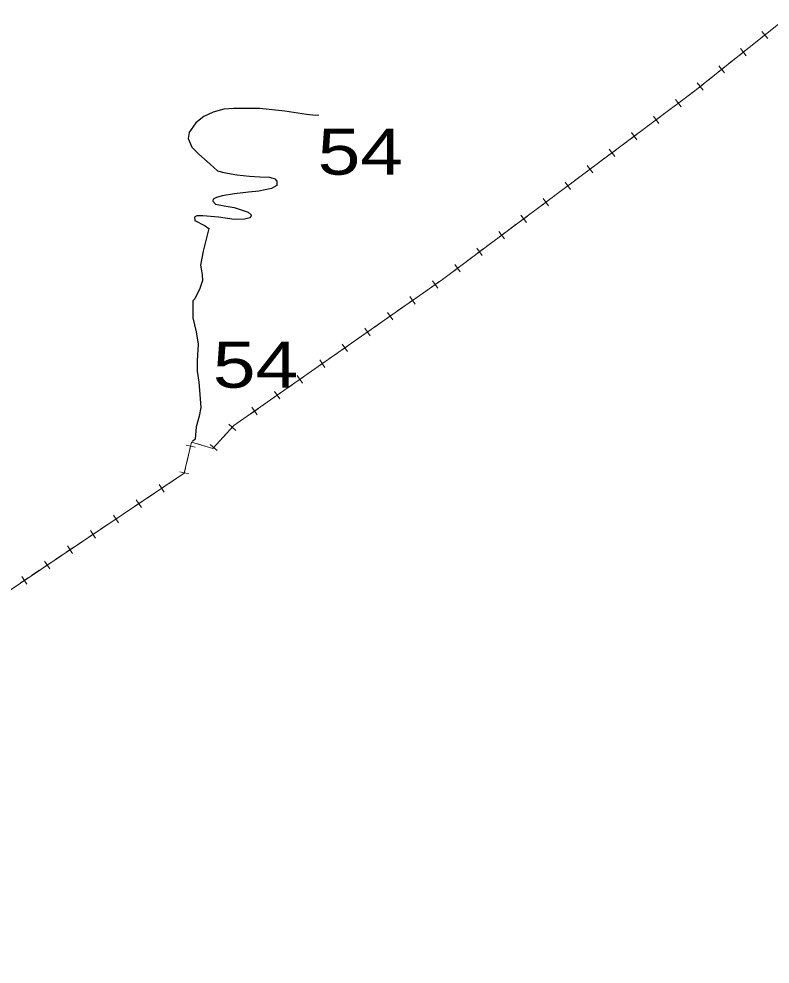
# Model space of a CAD drawing. Extents: x 476989 to 498418, y 4381813 to 4416555.
# Drawn here: x 486843 to 487660, y 4382283 to 4383311 of the extents above; entities that cross this region are included whole.
import ezdxf

# ---------------------------------------------------------------- set-up
doc = ezdxf.new("R2010")
doc.units = 0
doc.header["$LTSCALE"] = 20
for name, color, linetype, lineweight in [('13', 7, 'Continuous', 13), ('34', 7, 'Continuous', 13), ('6', 7, 'Continuous', 25)]:
    doc.layers.add(name, color=color, linetype=linetype, lineweight=lineweight)

msp = doc.modelspace()

# ---------------------------------------------------------------- linework, layer by layer
at = {"layer": '34'}
for p, q in [((487646.82, 4383287.64), (487639, 4383281.41)), ((487658.55, 4383296.99), (487650.73, 4383290.76)), ((487657.75, 4383289.96), (487651.52, 4383297.78)), ((487635.09, 4383278.3), (487627.27, 4383272.07)), ((487634.3, 4383271.27), (487628.07, 4383279.09)), ((487623.36, 4383268.95), (487615.54, 4383262.72)), ((487611.64, 4383259.61), (487603.82, 4383253.37)), ((487610.85, 4383252.58), (487604.61, 4383260.4)), ((487599.91, 4383250.26), (487592.09, 4383244.03)), ((487588.19, 4383240.92), (487580.37, 4383234.68)), ((487587.39, 4383233.89), (487581.16, 4383241.71)), ((487576.44, 4383231.58), (487568.43, 4383225.6)), ((487564.44, 4383222.61), (487556.43, 4383216.63)), ((487563.42, 4383215.61), (487557.44, 4383223.62)), ((487539.4, 4383197.66), (487533.41, 4383205.67)), ((487552.42, 4383213.63), (487544.41, 4383207.65)), ((487528.4, 4383195.68), (487520.39, 4383189.69)), ((487540.41, 4383204.66), (487532.4, 4383198.67)), ((487516.39, 4383186.71), (487508.38, 4383180.72)), ((487515.38, 4383179.71), (487509.39, 4383187.72)), ((487504.37, 4383177.73), (487496.36, 4383171.74)), ((487492.36, 4383168.76), (487484.35, 4383162.77)), ((487491.35, 4383161.76), (487485.37, 4383169.77)), ((487480.35, 4383159.78), (487472.34, 4383153.79)), ((487468.34, 4383150.8), (487460.33, 4383144.82)), ((487467.33, 4383143.81), (487461.34, 4383151.82)), ((487443.31, 4383125.85), (487437.32, 4383133.87)), ((487456.33, 4383141.83), (487448.31, 4383135.84)), ((487432.3, 4383123.87), (487424.29, 4383117.89)), ((487444.32, 4383132.85), (487436.31, 4383126.87)), ((487420.29, 4383114.9), (487412.28, 4383108.92)), ((487419.28, 4383107.9), (487413.3, 4383115.91)), ((487408.28, 4383105.92), (487400.27, 4383099.94)), ((487396.27, 4383096.95), (487388.26, 4383090.96)), ((487395.26, 4383089.95), (487389.27, 4383097.96)), ((487384.25, 4383087.97), (487376.24, 4383081.98)), ((487372.25, 4383079), (487364.24, 4383073.01)), ((487371.23, 4383072), (487365.25, 4383080.01)), ((487347.21, 4383054.05), (487341.22, 4383062.06)), ((487360.23, 4383070.02), (487352.22, 4383064.03)), ((487336.21, 4383052.07), (487328.2, 4383046.08)), ((487348.22, 4383061.05), (487340.21, 4383055.06)), ((487324.2, 4383043.09), (487316.19, 4383037.11)), ((487323.19, 4383036.1), (487317.2, 4383044.11)), ((487312.18, 4383034.12), (487304.17, 4383028.13)), ((487300.09, 4383025.26), (487291.9, 4383019.52)), ((487298.86, 4383018.3), (487293.13, 4383026.49)), ((487287.8, 4383016.66), (487279.61, 4383010.92)), ((487275.53, 4383008.06), (487267.34, 4383002.32)), ((487274.3, 4383001.09), (487268.56, 4383009.28)), ((487250.96, 4382990.85), (487242.77, 4382985.11)), ((487249.74, 4382983.89), (487244, 4382992.08)), ((487263.24, 4382999.45), (487255.05, 4382993.71)), ((487238.68, 4382982.24), (487230.49, 4382976.51)), ((487226.4, 4382973.64), (487218.21, 4382967.91)), ((487225.17, 4382966.68), (487219.43, 4382974.87)), ((487214.11, 4382965.04), (487205.92, 4382959.3)), ((487201.84, 4382956.44), (487193.64, 4382950.7)), ((487200.61, 4382949.48), (487194.87, 4382957.67)), ((487177.27, 4382939.23), (487169.08, 4382933.5)), ((487176.04, 4382932.27), (487170.31, 4382940.46)), ((487189.55, 4382947.83), (487181.36, 4382942.1)), ((487164.99, 4382930.63), (487156.79, 4382924.89)), ((487152.71, 4382922.03), (487144.52, 4382916.29)), ((487151.48, 4382915.06), (487145.74, 4382923.26)), ((487140.42, 4382913.42), (487132.23, 4382907.69)), ((487128.14, 4382904.82), (487119.95, 4382899.09)), ((487126.92, 4382897.86), (487121.18, 4382906.05)), ((487103.58, 4382887.62), (487095.39, 4382881.88)), ((487102.35, 4382880.65), (487096.62, 4382888.84)), ((487115.86, 4382896.22), (487107.67, 4382890.48)), ((487091.29, 4382879.01), (487083.1, 4382873.28)), ((487078.96, 4382863.75), (487071.6, 4382870.52)), ((487068.51, 4382859.77), (487061.74, 4382852.41)), ((487034.84, 4382845.47), (487025.1, 4382847.76)), ((487045.81, 4382846.49), (487036.25, 4382849.4)), ((487058.66, 4382841.68), (487051.3, 4382848.45)), ((487027.68, 4382836.88), (487025.39, 4382827.15)), ((487027.97, 4382816.28), (487018.23, 4382818.57)), ((487001.22, 4382796.4), (486995.66, 4382804.71)), ((487015.05, 4382811.68), (487006.74, 4382806.12)), ((486990.13, 4382795), (486981.82, 4382789.43)), ((487002.59, 4382803.34), (486994.28, 4382797.78)), ((486977.67, 4382786.66), (486969.36, 4382781.09)), ((486976.3, 4382779.72), (486970.73, 4382788.03)), ((486965.21, 4382778.31), (486956.9, 4382772.75)), ((486952.75, 4382769.97), (486944.44, 4382764.41)), ((486951.38, 4382763.04), (486945.81, 4382771.35)), ((486927.83, 4382753.29), (486919.52, 4382747.73)), ((486926.45, 4382746.36), (486920.89, 4382754.67)), ((486940.28, 4382761.63), (486931.97, 4382756.07)), ((486915.36, 4382744.95), (486907.05, 4382739.39)), ((486902.91, 4382736.61), (486894.6, 4382731.05)), ((486901.53, 4382729.67), (486895.97, 4382737.98)), ((486890.44, 4382728.27), (486882.13, 4382722.7)), ((486877.98, 4382719.93), (486869.67, 4382714.37)), ((486876.61, 4382712.99), (486871.05, 4382721.3)), ((486853.06, 4382703.25), (486844.75, 4382697.68)), ((486851.69, 4382696.31), (486846.13, 4382704.62)), ((486865.52, 4382711.58), (486857.21, 4382706.02))]:
    msp.add_line(p, q, dxfattribs=at)
for points in [[(487676.62, 4383311.4), (487577, 4383232), (487304, 4383028), (487077, 4382869), (487054, 4382844), (487031, 4382851), (487023, 4382817), (486778, 4382653), (486740, 4382634), (486629, 4382532), (486583, 4382537), (486557, 4382471), (486289, 4382313), (486283, 4382292), (486265, 4382283)], [(487079.02, 4382870.41), (487077, 4382869), (487071.9, 4382863.45)], [(487031.47, 4382850.86), (487031, 4382851), (487028.82, 4382841.75)], [(487058.36, 4382848.74), (487054, 4382844), (487050.6, 4382845.04)], [(487024.24, 4382822.29), (487023, 4382817), (487019.2, 4382814.46)]]:
    msp.add_lwpolyline(points, dxfattribs=at)
at = {"layer": '6'}
for points in [[(487169.41, 4383206.74), (487166.04, 4383206.21), (487156.02, 4383207.28), (487132.44, 4383211.07), (487105.23, 4383213.77), (487076.64, 4383213.95), (487066.01, 4383213.3), (487054.41, 4383209.96), (487044.4, 4383205.38), (487035.65, 4383198.23), (487028.06, 4383187.44)], [(487028.33, 4383187.82), (487027.14, 4383181.15), (487031.16, 4383171.92), (487038.79, 4383164.3), (487051.24, 4383153.47), (487059.28, 4383146.25), (487066.11, 4383144.25), (487080.17, 4383141.84), (487093.82, 4383140.24), (487105.07, 4383139.44), (487115.52, 4383139.04), (487121.54, 4383137.43), (487123.55, 4383135.02), (487123.55, 4383129.96), (487117.93, 4383126.75), (487104.27, 4383123.94), (487093.02, 4383122.74), (487077.76, 4383121.13), (487064.1, 4383118.72), (487058.07, 4383117.12), (487054.46, 4383115.11), (487054.05, 4383113.1), (487056.87, 4383109.89), (487066.51, 4383107.88), (487077.35, 4383106.28), (487087, 4383103.07), (487092.62, 4383101.06), (487095.83, 4383098.25), (487095.43, 4383096.24), (487094.23, 4383095.04), (487088.6, 4383093.43), (487077.35, 4383093.03), (487060.08, 4383095.84), (487043.21, 4383097.05), (487036.78, 4383097.05), (487033.97, 4383095.84), (487034.37, 4383092.23), (487045.62, 4383086.21), (487049.64, 4383083.4), (487043.61, 4383058.64), (487040.8, 4383043.38), (487041.2, 4383039.37), (487042.4, 4383032.95), (487042.85, 4383026.65), (487040.03, 4383018.22), (487034.41, 4383006.98), (487032.4, 4383004.57), (487032.4, 4382998.15), (487032.4, 4382986.11), (487036.02, 4382971.02), (487038.03, 4382957.37), (487036.82, 4382939.39), (487036.82, 4382928.15), (487038.83, 4382916.11), (487040.03, 4382902.87), (487040.84, 4382888.42), (487039.23, 4382879.18), (487036.02, 4382867.67), (487034.81, 4382854.02), (487032, 4382851.61)]]:
    msp.add_lwpolyline(points, dxfattribs=at)

# ---------------------------------------------------------------- texts
at = {"layer": '13', "width": 1.25}
for p in [(487168.07, 4383141.9), (487054.02, 4382910.13)]:
    msp.add_text('54', height=50, dxfattribs=at).set_placement(p)

doc.saveas('drawing.dxf')
